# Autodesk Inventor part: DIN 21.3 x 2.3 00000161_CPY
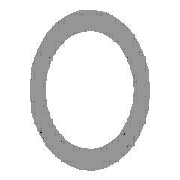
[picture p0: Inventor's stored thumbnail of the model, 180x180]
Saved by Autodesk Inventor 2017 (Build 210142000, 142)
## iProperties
Created: 2017-11
Part Number: DIN 21.3 x 2.3 00000161_CPY
Material: Steel, Mild
Description: Pipe
Document SubType Name: Modeling
Standard: DIN
Designer: iusti
Standard Revision: 2006-07
Standards Organization: DIN
Language: en-US
Size Designation: 21.3 x 2.3
Categories: <MemberInstance><Categories><Category DisplayName="Structural Shapes" InternalName="089c4875-fa83-4c05-b084-43b9cc11f5ed" Mnemonic="GRDR"><CategoryParameter Dis
Stock Number: 21.3 x 2.3
Density: 7.85 g/cm^3
Appearance: Semi-Polished
IsCustomPart: 1
G_L: 1500.000 mm
G_W: 21.300 mm
G_H: 21.300 mm
_CCFamilyMember: 1
_CCFamilyDisplayName: DIN EN 10210-2 - Pipe
_FrameMemberDoc: Frame Member File
_Version: 15.0.0
_GetPNFromCC: 1
Author: iusti
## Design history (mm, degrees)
node "Start plane"
node "End plane"
sketch "Sketch"
  geometry: C1 r 8.35 at (0, 0); C2 r 10.65 at (0, 0); 2 further points
  constraints: 3 coincident, 2 centre point
  dimensions: "d0" = 21.3 diameter of C2 (= G_H); "d1" = 2.3 radial gap between concentric circles of C2 C1 (= G_T)
extrude "Body" new body sketch "Sketch" stored distance "d2" = 1500 (= G_L); taper "d3" = 0 deg
node "Driven Length"
  sketch "Sketch3"
    geometry: L1 (0, 0)-(10, 0) reference
    constraints: 2 end point, 1 horizontal
  workplane "Work Plane3"
  sketch "Sketch4"
    geometry: L1 (-2, 0)-(12, 0) reference; L2 (-2, 1500)-(12, 1500) reference
    dimensions: "d7" = 1500 distance between parallel lines of L1 L2 (derived)
body "Solid1"
other parameters: "G_H" = 21.3 [user parameter; used in 1 equation term], "G_T" = 2.3 [user parameter; used in 1 equation term], "G_L" = 1500 (= d7) [user parameter; used in 1 equation term], "G_OFFSET_START" = 0 [user parameter; used in 1 equation term], "G_OFFSET_END" = 0 [user parameter; used in 1 equation term], "d4" = 0 (computed from G_OFFSET_START), "d6" = 90 deg
